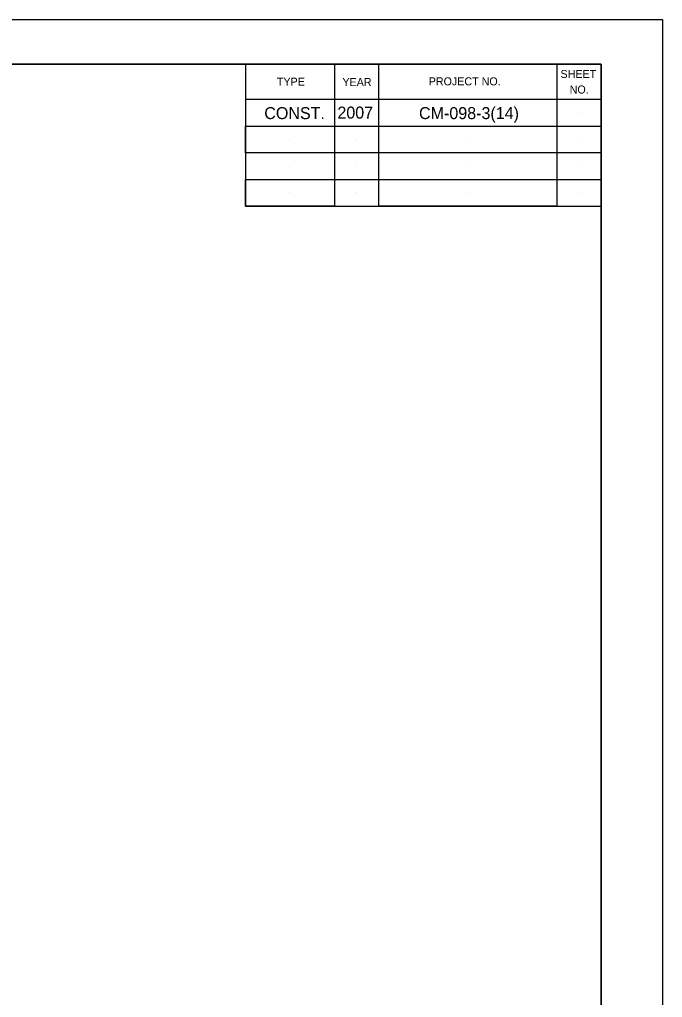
# Model space of a CAD drawing. Extents: x 1623795.1 to 1623879, y 427353.8 to 427391.8.
# Drawn here: x 1623863.67 to 1623870.9, y 427378.86 to 427389.86 of the extents above; entities that cross this region are included whole.
import ezdxf

# ---------------------------------------------------------------- set-up
doc = ezdxf.new("R2010")
doc.units = 0
for name, color, linetype in [('DESIGN - PUBLIC HEARING - Shapes', 7, 'Continuous'), ('DESIGN - SCRATCH - User 1', 7, 'Continuous'), ('DESIGN - SHEET - Corner Text', 7, 'Continuous'), ('DESIGN - SHEET - Linework', 7, 'Continuous'), ('DESIGN - SHEET - Plot Shape', 7, 'Continuous')]:
    doc.layers.add(name, color=color, linetype=linetype)

msp = doc.modelspace()

# ---------------------------------------------------------------- linework, layer by layer
at = {"layer": 'DESIGN - PUBLIC HEARING - Shapes'}
msp.add_lwpolyline([(1623838.215, 427368.358), (1623870.215, 427368.358), (1623870.215, 427389.358), (1623838.215, 427389.358)], close=True, dxfattribs=at)
at = {"layer": 'DESIGN - SCRATCH - User 1'}
for p, q in [((1623866.715, 427388.808), (1623866.715, 427388.808)), ((1623867.456, 427388.808), (1623867.456, 427388.808)), ((1623868.705, 427388.808), (1623868.705, 427388.808)), ((1623869.955, 427388.808), (1623869.955, 427388.808)), ((1623866.715, 427388.508), (1623866.715, 427388.508)), ((1623867.456, 427388.508), (1623867.456, 427388.508)), ((1623868.705, 427388.508), (1623868.705, 427388.508)), ((1623869.955, 427388.508), (1623869.955, 427388.508)), ((1623866.715, 427388.207), (1623866.715, 427388.207)), ((1623867.456, 427388.207), (1623867.456, 427388.207)), ((1623868.705, 427388.207), (1623868.705, 427388.207)), ((1623869.955, 427388.207), (1623869.955, 427388.207)), ((1623866.715, 427387.908), (1623866.715, 427387.908)), ((1623867.456, 427387.908), (1623867.456, 427387.908)), ((1623868.705, 427387.908), (1623868.705, 427387.908)), ((1623869.955, 427387.908), (1623869.955, 427387.908))]:
    msp.add_line(p, q, dxfattribs=at)
msp.add_lwpolyline([(1623836.514, 427389.358), (1623870.215, 427389.358), (1623870.215, 427368.358), (1623836.514, 427368.358)], close=True, dxfattribs=at)
at = {"layer": 'DESIGN - SHEET - Linework'}
for p, q in [((1623870.215, 427389.358), (1623838.215, 427389.358)), ((1623870.215, 427368.358), (1623870.215, 427389.358))]:
    msp.add_line(p, q, dxfattribs=at)
msp.add_lwpolyline([(1623866.215, 427389.357), (1623866.215, 427387.758), (1623870.215, 427387.758), (1623870.215, 427389.357), (1623869.716, 427389.357), (1623869.716, 427387.758), (1623867.715, 427387.758), (1623867.715, 427389.357), (1623867.214, 427389.357), (1623867.214, 427387.758), (1623866.215, 427387.758), (1623866.215, 427388.057), (1623870.215, 427388.057), (1623870.215, 427388.358), (1623866.215, 427388.358), (1623866.215, 427388.658), (1623870.215, 427388.658), (1623870.215, 427388.957), (1623866.215, 427388.957)], dxfattribs=at)
at = {"layer": 'DESIGN - SHEET - Plot Shape'}
msp.add_lwpolyline([(1623834.903, 427389.858), (1623870.903, 427389.858), (1623870.903, 427367.858), (1623834.903, 427367.858)], close=True, dxfattribs=at)

# ---------------------------------------------------------------- texts
at = {"layer": 'DESIGN - SHEET - Corner Text'}
for s, p in [('CONST.', (1623866.426, 427388.738)), ('2007', (1623867.248, 427388.744)), ('CM-098-3(14)', (1623868.166, 427388.738))]:
    msp.add_text(s, height=0.135, dxfattribs=at).set_placement(p)
at = {"layer": 'DESIGN - SHEET - Linework'}
for s, p in [('SHEET', (1623869.757, 427389.201)), ('TYPE', (1623866.568, 427389.114)), ('YEAR', (1623867.305, 427389.11)), ('PROJECT NO.', (1623868.275, 427389.118)), ('NO.', (1623869.86, 427389.026))]:
    msp.add_text(s, height=0.09, dxfattribs=at).set_placement(p)

doc.saveas('drawing.dxf')
